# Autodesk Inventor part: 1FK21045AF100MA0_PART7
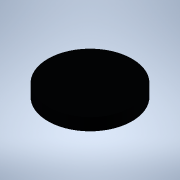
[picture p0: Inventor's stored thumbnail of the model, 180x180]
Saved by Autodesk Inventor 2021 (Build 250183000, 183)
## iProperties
Created: 2025-04
Part Number: 1FK21045AF100MA0_PART7
Material: Generic
Catalog Web Link: www.3dfindit.com
Description: -Servo synchronous motor
Document SubType Name: Modeling
Designer: psAdmin
Mass: 0.299142 g
Surface Area: 3.8585 cm^2
Volume: 0.299142 cm^3
Density: 1 g/cm^3
Appearance: PSOLRGB-38-46-56
Category: PARTsolutions
Title: 1FK21045AF100MA0_PART7
Author: Cadenas PARTsolutions
Comments: Servo synchronous motor
Sending System: PARTsolutions
Preprocessor: ST-DEVELOPER v19.3
PSOL_IDENT_0: {$CADENAS_DATA/23d-libs/siemens_ag/_cat_/52/6b/1fk21045af100ma0.prj},213 {VTYP=3D},{NB=1FK21045AF100
PSOL_IDENT_1: MA0_PART7},{LINA=1FK21045AF100MA0_PART7},{NN=1FK21045AF100MA0_PART7},{NOPRJ=TRUE},{DATE=19.08.2025 1
PSOL_IDENT_2: 4:00:38},{GEOMDATE=30.07.2025 02:01:45},{VERSION=},{LINEID=10},{WBVAR=},{WBNUMERIC=}  {NB=1FK21045AF
PSOL_IDENT_3: 100MA0_PART7},{LINA=1FK21045AF100MA0_PART7},{KT=DUMMY},{PREVIEW=../../../_pool_/cb/72/p_d211_xx_0043
PSOL_IDENT_4: 4j.png},{DESCSHORT=SIMOTICS S-1FK2 HD, SINAMICS S210 3AC 400V-480V, 2.4 Nm, 3000 rpm},{DESCLONG=SIMO
PSOL_IDENT_5: TICS S-1FK2 HD servo motor M0=2.4 Nm; PN = 0.75 kW at nN=3000 rpm (380-480 V); PN = 0.375 kW at nN=1
PSOL_IDENT_6: 500 rpm (200-240 V); with holding brake; degree of protection IP64; cylindrical shaft D19x40mm; abso
PSOL_IDENT_7: lute encoder 22-bit + 12-bit multiturn (encoder AM22DQC); with OCC interface; plug size M17, rotatab
PSOL_IDENT_8: le; SIMOTICS S-1FK2 servomotorfor a wide range of uses in industrial environments. SIMOTICS S‑1FK2 s
PSOL_IDENT_9: ervomotors are compact synchronous motors with a high dynamic performance that set themselves apart
PSOL_IDENT_10: as a result of their high power density, degree of protection and overload capability. The motors ar
PSOL_IDENT_11: e available in two variants: as High Dynamic variant (highest dynamic performance as a result of the
PSOL_IDENT_12: low intrinsic moment of inertia for applications demanding a high dynamic performance with low move
PSOL_IDENT_13: d masses) - and as Compact variant (precise and stable closed-loop control for medium up to large mo
PSOL_IDENT_14: ved masses as a result of a medium intrinsic moment of inertia). SIMOTICSS‑1FK2 servomotors fully ex
PSOL_IDENT_15: ploit their strengths in a system with the SINAMICSS210 frequency converter and simple connection us
PSOL_IDENT_16: ing the one cable connection (OCC). Advantages include the short control and positioning times, fast
PSOL_IDENT_17: and precise correction of disturbing quantities as well as stable control with a high dynamic perfo
PSOL_IDENT_18: rmance. The servo motors can be configured to address a wide range of requirements. For example with
PSOL_IDENT_19: and without holding brake, IP64 or IP65 degree of protection, singleturn or multiturn absolute enco
PSOL_IDENT_20: ders - to name just a few. Further, the servomotors are available in different shaft heights extendi
PSOL_IDENT_21: ng from 20 to 100. A shaft sealing ring is available to achieve an IP65 degree of protection and for
PSOL_IDENT_22: subsequent mounting at the motor or as spare part. SIMOTICS - the optimum motor for each and every
PSOL_IDENT_23: motion control application.},{INTNO=804766906411},{SUPPLIERALTNO=1FK2104-5AF10-0MA0},{MANUID=1FK2104
PSOL_IDENT_24: 5AF100MA0},{MANUNAME=Siemens},{MANUTYPEDESC=Synchronous motor 1FK2-HD 2.4 NM},{AAU732=SIMOTICS},{AAO
PSOL_IDENT_25: 057=S-1FK2},{AAU734=SIMOTICS S-1FK2 HD servo motor M0=2.4 Nm; PN = 0.75 kW at nN=3000 rpm (380-480 V
PSOL_IDENT_26: ); PN = 0.375 kW at nN=1500 rpm (200-240 V); with holding brake; degree of protection IP64; cylindri
PSOL_IDENT_27: cal shaft D19x40mm; absolute encoder 22-bit + 12-bit multiturn (encoder AM22DQC); with OCC interface
PSOL_IDENT_28: ; plug size M17, rotatable;},{AAW338=Synchronous motor 1FK2-HD 2.4 NM},{AAO742=SIMOTICS},{AAO663=404
PSOL_IDENT_29: 2948693070},{NOCUPEROU=1},{PRICEQUANTITY=1},{QUANTITYMIN=1},{QUANTITYINT=1},{CTN=85015100},{COO=DE},
PSOL_IDENT_30: {AAO676=1FK2104-5AF10-0MA0},{AAO677=Siemens AG},{ORDERUNIT=C62},{CONTENTUNIT=C62}
NB: 1FK21045AF100MA0_PART7
NT: Servo synchronous motor
NBSYN: $MANUID._PART7
LINA: 1FK21045AF100MA0_PART7
CATALOG: SIEMENS
PREVIEW: ../../../_pool_/cb/72/p_d211_xx_00434j.png
DESCSHORT: SIMOTICS S-1FK2 HD, SINAMICS S210 3AC 400V-480V, 2.4 Nm, 3000 rpm
DESCLONG: SIMOTICS S-1FK2 HD servo motor M0=2.4 Nm; PN = 0.75 kW at nN=3000 rpm (380-480 V); PN = 0.375 kW at nN=1500 rpm (200-240 V); with holding brake; degree of prote
INTNO: 804766906411
SUPPLIERALTNO: 1FK2104-5AF10-0MA0
MANUID: 1FK21045AF100MA0
MANUNAME: Siemens
MANUTYPEDESC: Synchronous motor 1FK2-HD 2.4 NM
AAU732: SIMOTICS
AAO057: S-1FK2
AAU734: SIMOTICS S-1FK2 HD servo motor M0=2.4 Nm; PN = 0.75 kW at nN=3000 rpm (380-480 V); PN = 0.375 kW at nN=1500 rpm (200-240 V); with holding brake; degree of prote
AAW338: Synchronous motor 1FK2-HD 2.4 NM
AAO742: SIMOTICS
AAO663: 4042948693070.0
NOCUPEROU: 1
PRICEQUANTITY: 1
QUANTITYMIN: 1
QUANTITYINT: 1
CTN: 85015100
COO: DE
ARTICLENO: 1FK21045AF100MA0_PART7
BOMINFO: 1FK21045AF100MA0_PART7
CREATOR: CADENAS GmbH
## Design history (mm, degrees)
feature "2025_04_17_15_34_52_0286"
body "Solid1"
